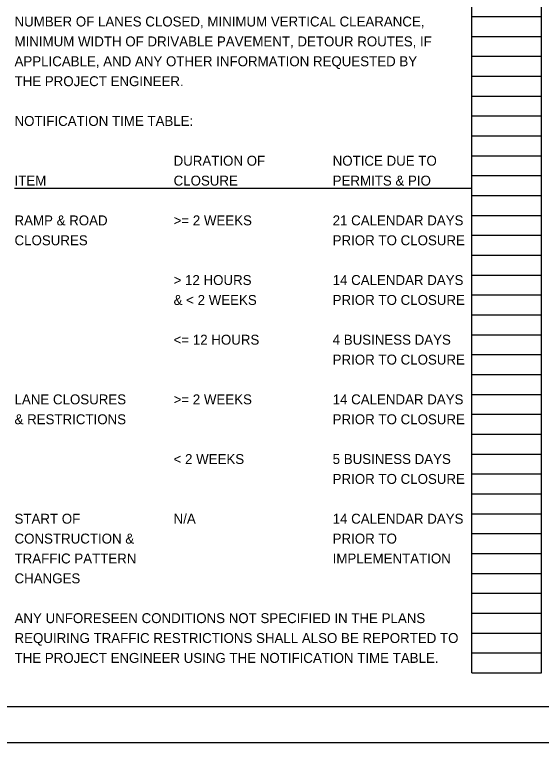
# Model space of a CAD drawing. Extents: x -50 to 112, y -27 to 22.
# Drawn here: x 95.24 to 102.66, y 0 to 10.25 of the extents above; entities that cross this region are included whole.
import ezdxf

# ---------------------------------------------------------------- set-up
doc = ezdxf.new("R2010")
doc.units = 0
for name, color, linetype in [('SC_Scratch1', 7, 'Continuous'), ('SH_Border', 7, 'Continuous'), ('SH_Cut_Line', 7, 'Continuous'), ('SH_Text', 7, 'Continuous')]:
    doc.layers.add(name, color=color, linetype=linetype)

msp = doc.modelspace()

# ---------------------------------------------------------------- linework, layer by layer
at = {"layer": 'SC_Scratch1'}
for p, q in [((101.68, 0.98), (101.68, 21.14)), ((102.66, 0.98), (102.66, 21.14)), ((101.68, 10.22), (102.66, 10.22)), ((101.68, 9.94), (102.66, 9.94)), ((101.68, 9.66), (102.66, 9.66)), ((101.68, 9.38), (102.66, 9.38)), ((101.68, 9.1), (102.66, 9.1)), ((101.68, 8.82), (102.66, 8.82)), ((101.68, 8.54), (102.66, 8.54)), ((101.68, 8.26), (102.66, 8.26)), ((101.68, 7.98), (102.66, 7.98)), ((101.68, 7.7), (102.66, 7.7)), ((101.68, 7.42), (102.66, 7.42)), ((101.68, 7.14), (102.66, 7.14)), ((101.68, 6.86), (102.66, 6.86)), ((101.68, 6.58), (102.66, 6.58)), ((101.68, 6.3), (102.66, 6.3)), ((101.68, 6.02), (102.66, 6.02)), ((101.68, 5.74), (102.66, 5.74)), ((101.68, 5.46), (102.66, 5.46)), ((101.68, 5.18), (102.66, 5.18)), ((101.68, 4.9), (102.66, 4.9)), ((101.68, 4.62), (102.66, 4.62)), ((101.68, 4.34), (102.66, 4.34)), ((101.68, 4.06), (102.66, 4.06)), ((101.68, 3.78), (102.66, 3.78)), ((101.68, 3.5), (102.66, 3.5)), ((101.68, 3.22), (102.66, 3.22)), ((101.68, 2.94), (102.66, 2.94)), ((101.68, 2.66), (102.66, 2.66)), ((101.68, 2.38), (102.66, 2.38)), ((101.68, 2.1), (102.66, 2.1)), ((101.68, 1.82), (102.66, 1.82)), ((101.68, 1.54), (102.66, 1.54)), ((101.68, 1.26), (102.66, 1.26)), ((101.68, 0.98), (102.66, 0.98))]:
    msp.add_line(p, q, dxfattribs=at)
at = {"layer": 'SH_Border'}
msp.add_lwpolyline([(79.5, 21.5), (111.5, 21.5), (111.5, 0.5), (79.5, 0.5)], close=True, dxfattribs=at)
at = {"layer": 'SH_Cut_Line'}
msp.add_lwpolyline([(78, 0), (112, 0), (112, 22), (78, 22)], close=True, dxfattribs=at)
at = {"layer": 'SH_Text'}
msp.add_line((95.24, 7.805), (101.68, 7.805), dxfattribs=at)

# ---------------------------------------------------------------- texts
for s, p in [('NUMBER OF LANES CLOSED, MINIMUM VERTICAL CLEARANCE, ', (95.24, 10.08)), ('MINIMUM WIDTH OF DRIVABLE PAVEMENT, DETOUR ROUTES, IF ', (95.24, 9.8)), ('APPLICABLE, AND ANY OTHER INFORMATION REQUESTED BY ', (95.24, 9.52)), ('THE PROJECT ENGINEER.', (95.24, 9.24)), ('NOTIFICATION TIME TABLE:', (95.24, 8.68)), ('DURATION OF ', (97.48, 8.12)), ('NOTICE DUE TO', (99.72, 8.12)), ('ITEM ', (95.24, 7.84)), ('CLOSURE ', (97.48, 7.84)), ('PERMITS & PIO', (99.72, 7.84)), ('RAMP & ROAD ', (95.24, 7.28)), ('>= 2 WEEKS ', (97.48, 7.28)), ('21 CALENDAR DAYS', (99.72, 7.28)), ('CLOSURES ', (95.24, 7)), ('PRIOR TO CLOSURE', (99.72, 7)), ('> 12 HOURS ', (97.48, 6.44)), ('14 CALENDAR DAYS', (99.72, 6.44)), ('& < 2 WEEKS ', (97.48, 6.16)), ('PRIOR TO CLOSURE', (99.72, 6.16)), ('<= 12 HOURS ', (97.48, 5.6)), ('4 BUSINESS DAYS', (99.72, 5.6)), ('PRIOR TO CLOSURE', (99.72, 5.32)), ('LANE CLOSURES ', (95.24, 4.76)), ('>= 2 WEEKS ', (97.48, 4.76)), ('14 CALENDAR DAYS', (99.72, 4.76)), ('& RESTRICTIONS ', (95.24, 4.48)), ('PRIOR TO CLOSURE', (99.72, 4.48)), ('< 2 WEEKS ', (97.48, 3.92)), ('5 BUSINESS DAYS', (99.72, 3.92)), ('PRIOR TO CLOSURE', (99.72, 3.64)), ('START OF ', (95.24, 3.08)), ('N/A ', (97.48, 3.08)), ('14 CALENDAR DAYS', (99.72, 3.08)), ('CONSTRUCTION & ', (95.24, 2.8)), ('PRIOR TO', (99.72, 2.8)), ('TRAFFIC PATTERN ', (95.24, 2.52)), ('IMPLEMENTATION', (99.72, 2.52)), ('CHANGES', (95.24, 2.24)), ('ANY UNFORESEEN CONDITIONS NOT SPECIFIED IN THE PLANS ', (95.24, 1.68)), ('REQUIRING TRAFFIC RESTRICTIONS SHALL ALSO BE REPORTED TO ', (95.24, 1.4)), ('THE PROJECT ENGINEER USING THE NOTIFICATION TIME TABLE.', (95.24, 1.12))]:
    msp.add_text(s, height=0.14, dxfattribs=at).set_placement(p)

doc.saveas('drawing.dxf')
